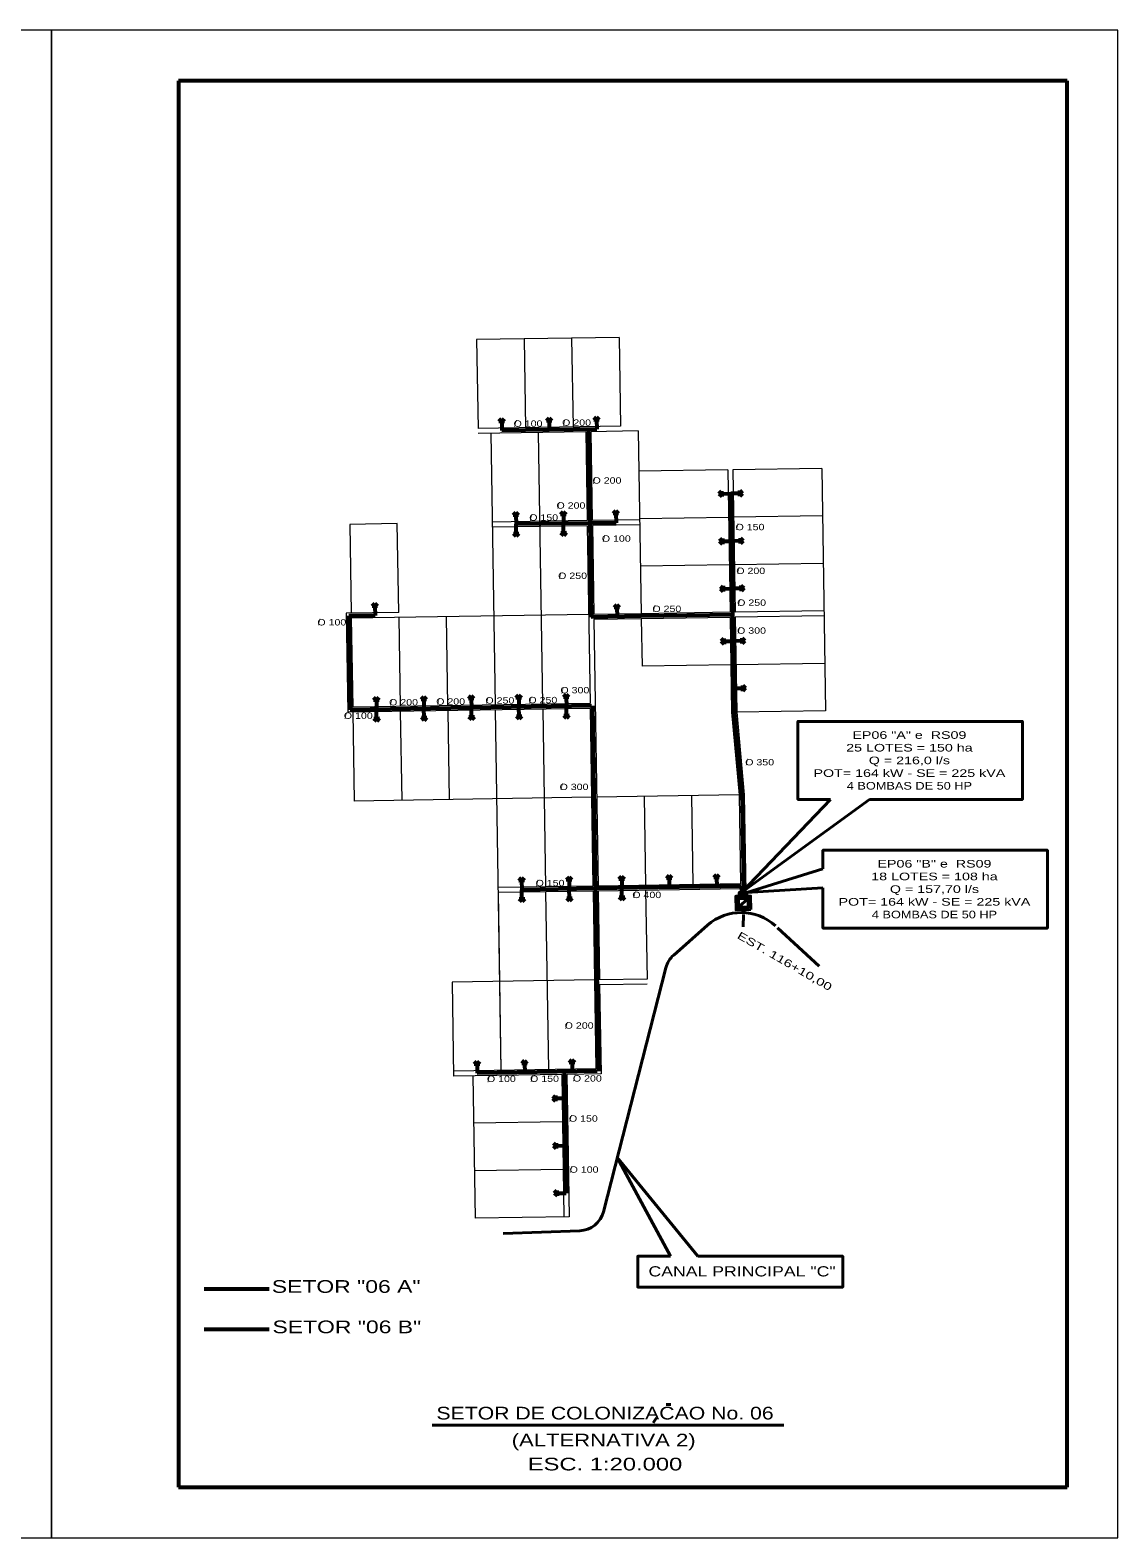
# Model space of a CAD drawing. Extents: x 312964 to 351929, y 9004151 to 9034973.
# Drawn here: x 317080 to 321364, y 9004477 to 9010417 of the extents above; entities that cross this region are included whole.
import ezdxf
from ezdxf.enums import TextEntityAlignment as Align

# ---------------------------------------------------------------- set-up
doc = ezdxf.new("R2010")
doc.units = 0
doc.header["$LTSCALE"] = 10
doc.layers.add('1', color=7, linetype='Continuous', lineweight=13)
doc.layers.add('2', color=7, linetype='Continuous', lineweight=53)

msp = doc.modelspace()

# ---------------------------------------------------------------- linework, layer by layer
at = {"layer": '1', "lineweight": 53}
for p, q in [((317663.57, 9010216.73), (317663.57, 9004676.73)), ((321163.57, 9010216.73), (317663.57, 9010216.73)), ((321163.57, 9004676.73), (321163.57, 9010216.73)), ((319852.53, 9007729.07), (319884.12, 9007376.36)), ((319884.12, 9007376.36), (319889.77, 9007019.76)), ((319880.39, 9007043.79), (319880.77, 9007019.64)), ((317764.64, 9005457.55), (318020.59, 9005457.55)), ((317764.64, 9005298.54), (318020.59, 9005298.54)), ((317663.57, 9004676.73), (321163.57, 9004676.73))]:
    msp.add_line(p, q, dxfattribs=at)
at = {"layer": '1'}
for p, q in [((319399.07, 9009206.44), (318838.14, 9009197.55)), ((319025.12, 9009200.51), (319030.66, 9008850.56)), ((319212.09, 9009203.47), (319217.64, 9008853.52)), ((319399.07, 9009206.44), (319404.62, 9008856.48)), ((318838.14, 9009197.55), (318843.69, 9008847.59)), ((319404.62, 9008856.48), (318843.69, 9008847.59)), ((319267.95, 9008834.31), (318844, 9008827.6)), ((318894, 9008828.39), (318910.94, 9007758.52)), ((319080.97, 9008831.35), (319097.92, 9007761.49)), ((319267.95, 9008834.31), (319273.49, 9008484.36)), ((319474.92, 9008837.59), (319287.95, 9008834.63)), ((319287.95, 9008834.63), (319293.49, 9008484.67)), ((319474.92, 9008837.59), (319486.33, 9008117.68)), ((319827.4, 9008684.16), (319477.44, 9008678.61)), ((320197.35, 9008690.02), (319847.4, 9008684.47)), ((319847.4, 9008684.47), (319856.28, 9008123.54)), ((320197.35, 9008690.02), (320212.48, 9007735.14)), ((319480.47, 9008487.64), (319293.49, 9008484.67)), ((319830.36, 9008497.18), (319480.4, 9008491.64)), ((320200.31, 9008503.04), (319850.36, 9008497.5)), ((318525.59, 9008472.51), (318338.61, 9008469.55)), ((318338.61, 9008469.55), (318344.15, 9008119.59)), ((318531.13, 9008122.55), (318525.59, 9008472.51)), ((319273.49, 9008484.36), (318899.54, 9008478.43)), ((319273.81, 9008464.36), (318899.86, 9008458.44)), ((319273.81, 9008464.36), (319284.9, 9007764.45)), ((319480.78, 9008467.64), (319293.81, 9008464.68)), ((319293.81, 9008464.68), (319299.35, 9008114.72)), ((319833.32, 9008310.2), (319483.37, 9008304.66)), ((320203.28, 9008316.06), (319853.32, 9008310.52)), ((320206.24, 9008129.09), (319856.28, 9008123.54)), ((318531.13, 9008122.55), (318324.16, 9008119.27)), ((318324.16, 9008119.27), (318330.33, 9007729.32)), ((319279.35, 9008114.4), (318344.47, 9008099.59)), ((318344.47, 9008099.59), (318350.02, 9007749.64)), ((318531.45, 9008102.56), (318536.99, 9007752.6)), ((318718.42, 9008105.52), (318723.97, 9007755.56)), ((319486.33, 9008117.68), (319299.35, 9008114.72)), ((319486.64, 9008097.68), (319299.67, 9008094.72)), ((319299.67, 9008094.72), (319316.3, 9007044.85)), ((319836.6, 9008103.23), (319486.64, 9008097.68)), ((319486.64, 9008097.68), (319489.61, 9007910.71)), ((319836.6, 9008103.23), (319842.53, 9007729.28)), ((320206.55, 9008109.09), (319856.6, 9008103.55)), ((319856.6, 9008103.55), (319862.52, 9007729.59)), ((319839.56, 9007916.25), (319489.61, 9007910.71)), ((320209.52, 9007922.11), (319859.56, 9007916.57)), ((319285.21, 9007744.45), (318330.33, 9007729.32)), ((319284.9, 9007764.45), (318350.02, 9007749.64)), ((318350.33, 9007729.64), (318355.88, 9007379.68)), ((318537.31, 9007732.6), (318542.85, 9007382.65)), ((318724.28, 9007735.56), (318729.83, 9007385.61)), ((318911.26, 9007738.53), (318933.75, 9006318.7)), ((319098.24, 9007741.49), (319109.33, 9007041.58)), ((319285.21, 9007744.45), (319296.3, 9007044.54)), ((319842.53, 9007729.28), (319871.69, 9007403.7)), ((320212.48, 9007735.14), (319862.52, 9007729.59)), ((319862.52, 9007729.59), (319891.68, 9007404.01)), ((319290.76, 9007394.49), (318355.88, 9007379.68)), ((319871.69, 9007403.7), (319310.76, 9007394.81)), ((319497.73, 9007397.77), (319503.28, 9007047.82)), ((319684.71, 9007400.73), (319690.25, 9007050.78)), ((319871.69, 9007403.7), (319877.23, 9007053.74)), ((319891.68, 9007404.01), (319897.77, 9007019.78)), ((319296.3, 9007044.54), (318922.35, 9007038.61)), ((319296.62, 9007024.54), (318922.67, 9007018.62)), ((318922.67, 9007018.62), (318933.75, 9006318.7)), ((319109.64, 9007021.58), (319120.73, 9006321.67)), ((319296.62, 9007024.54), (319307.71, 9006324.63)), ((319877.23, 9007053.74), (319316.3, 9007044.85)), ((319877.55, 9007033.74), (319316.62, 9007024.86)), ((319316.62, 9007024.86), (319322.16, 9006674.9)), ((319503.59, 9007027.82), (319509.14, 9006677.86)), ((319877.55, 9007033.74), (319877.77, 9007019.5)), ((319302.16, 9006674.58), (318741.23, 9006665.7)), ((318741.23, 9006665.7), (318747.09, 9006295.74)), ((319509.14, 9006677.86), (319322.16, 9006674.9)), ((319509.45, 9006657.87), (319322.48, 9006654.9)), ((319322.48, 9006654.9), (319328.02, 9006304.95)), ((319307.71, 9006324.63), (318746.78, 9006315.74)), ((319173.04, 9006302.49), (318747.09, 9006295.74)), ((318823.08, 9006296.95), (318831.97, 9005736.02)), ((319173.04, 9006302.49), (319181.93, 9005741.56)), ((319328.02, 9006304.95), (319193.04, 9006302.81)), ((319193.04, 9006302.81), (319201.92, 9005741.88)), ((319176, 9006115.52), (318826.05, 9006109.97)), ((319178.96, 9005928.54), (318829.01, 9005923)), ((319178.96, 9005928.54), (318829.01, 9005923)), ((319201.92, 9005741.88), (318831.97, 9005736.02))]:
    msp.add_line(p, q, dxfattribs=at)
at = {"layer": '1', "lineweight": 40}
for p, q in [((319887.61, 9007004.64), (319872.4, 9007019.42)), ((319872.61, 9007004.42), (319887.4, 9007019.63)), ((319902.61, 9007004.85), (319887.4, 9007019.63)), ((319887.61, 9007004.64), (319902.4, 9007019.85)), ((319907.4, 9006995.02), (319869.56, 9006961.09)), ((319614.3, 9006772.99), (319747.49, 9006890.41)), ((320187.35, 9006728.93), (320023.1, 9006880.27)), ((319337.26, 9005761.56), (319583.56, 9006722.8)), ((318943.23, 9005675.63), (319243.99, 9005686.44)), ((319584.39, 9005001.87), (319602.68, 9005001.87)), ((319546.4, 9004949.78), (319533.74, 9004930.07)), ((318663.13, 9004920.21), (320047.47, 9004920.21))]:
    msp.add_line(p, q, dxfattribs=at)
at = {"layer": '1'}
for points in [[(312963.57, 9010416.73), (312963.57, 9004476.73), (317163.57, 9004476.73), (317163.57, 9010416.73)], [(317163.57, 9010416.73), (317163.57, 9004476.73), (321363.57, 9004476.73), (321363.57, 9010416.73)]]:
    msp.add_lwpolyline(points, close=True, dxfattribs=at)
msp.add_lwpolyline([(319827.4, 9008684.16), (319836.28, 9008123.23), (319486.33, 9008117.68)], dxfattribs=at)
at = {"layer": '1', "lineweight": 40}
for points in [[(319918.02, 9006951.78), (319859.7, 9006950.94), (319858.94, 9007004.33), (319917.26, 9007005.16)], [(319887.4, 9007019.63), (319872.4, 9007019.42), (319872.61, 9007004.42), (319887.61, 9007004.64)], [(319902.4, 9007019.85), (319887.4, 9007019.63), (319887.61, 9007004.64), (319902.61, 9007004.85)], [(319907.88, 9006961.63), (319869.56, 9006961.09), (319869.08, 9006994.47), (319907.4, 9006995.02)], [(319907.4, 9006995.02), (319907.88, 9006961.63), (319869.56, 9006961.09)]]:
    msp.add_lwpolyline(points, close=True, dxfattribs=at)
for points in [[(319602.16, 9005585.86), (319392.1, 9005975.58), (319709.08, 9005585.86)], [(319709.08, 9005585.86), (320280.26, 9005585.86), (320280.26, 9005464.79), (319472.73, 9005464.79), (319472.73, 9005585.86), (319602.16, 9005585.86)]]:
    msp.add_lwpolyline(points, dxfattribs=at)
for centre, radius, start, end in [((319879.75, 9006740.39), 200, 47.34258, 131.40088), ((319680.43, 9006697.98), 100, 131.40087, 165.62837), ((319240.39, 9005786.38), 100, 272.05855, 345.62833)]:
    msp.add_arc(centre, radius, start, end, dxfattribs=at)
at = {"layer": '2'}
for p, q in [((318936.34, 9008885.69), (318925.73, 9008874.75)), ((318947.28, 9008875.09), (318925.73, 9008874.75)), ((318936.34, 9008885.69), (318947.28, 9008875.09)), ((318936.76, 9008874.92), (318937.33, 9008839.08)), ((319311.29, 9008845), (318937.33, 9008839.08)), ((319123.31, 9008888.66), (319112.7, 9008877.71)), ((319134.26, 9008878.05), (319112.7, 9008877.71)), ((319123.31, 9008888.66), (319134.26, 9008878.05)), ((319123.74, 9008877.88), (319124.31, 9008842.04)), ((319277.79, 9008844.47), (319283.49, 9008484.52)), ((319310.29, 9008891.62), (319299.68, 9008880.67)), ((319321.24, 9008881.01), (319299.68, 9008880.67)), ((319310.29, 9008891.62), (319321.24, 9008881.01)), ((319310.72, 9008880.84), (319311.29, 9008845)), ((319792.26, 9008589.83), (319802.87, 9008600.78)), ((319792.26, 9008589.83), (319803.21, 9008579.22)), ((319802.87, 9008600.78), (319803.21, 9008579.22)), ((319803.03, 9008590.26), (319838.88, 9008590.83)), ((319874.72, 9008591.39), (319838.88, 9008590.83)), ((319838.88, 9008590.83), (319846.44, 9008113.39)), ((319874.89, 9008580.87), (319874.55, 9008602.43)), ((319885.5, 9008591.82), (319874.55, 9008602.43)), ((319885.5, 9008591.82), (319874.89, 9008580.87)), ((318992.19, 9008516.53), (318981.58, 9008505.58)), ((319003.14, 9008505.93), (318981.58, 9008505.58)), ((318992.19, 9008516.53), (319003.14, 9008505.93)), ((318992.62, 9008505.76), (318993.19, 9008469.92)), ((319179.17, 9008519.49), (319168.56, 9008508.55)), ((319190.11, 9008508.89), (319168.56, 9008508.55)), ((319179.17, 9008519.49), (319190.11, 9008508.89)), ((319179.6, 9008508.72), (319180.16, 9008472.88)), ((319386.14, 9008522.77), (319375.53, 9008511.82)), ((319397.09, 9008512.17), (319375.53, 9008511.82)), ((319386.14, 9008522.77), (319397.09, 9008512.17)), ((319386.57, 9008512), (319387.14, 9008476.16)), ((318983.23, 9008433.9), (319004.79, 9008434.25)), ((318994.18, 9008423.3), (318983.23, 9008433.9)), ((318993.75, 9008434.07), (318993.19, 9008469.92)), ((318994.18, 9008423.3), (319004.79, 9008434.25)), ((319170.21, 9008436.87), (319191.77, 9008437.21)), ((319181.16, 9008426.26), (319170.21, 9008436.87)), ((319180.73, 9008437.03), (319180.16, 9008472.88)), ((319181.16, 9008426.26), (319191.77, 9008437.21)), ((319283.49, 9008484.52), (319289.51, 9008104.56)), ((319795.22, 9008402.85), (319805.83, 9008413.8)), ((319795.22, 9008402.85), (319806.17, 9008392.24)), ((319805.83, 9008413.8), (319806.17, 9008392.24)), ((319806, 9008403.28), (319841.84, 9008403.85)), ((319877.68, 9008404.42), (319841.84, 9008403.85)), ((319877.85, 9008393.9), (319877.51, 9008415.45)), ((319888.46, 9008404.85), (319877.51, 9008415.45)), ((319888.46, 9008404.85), (319877.85, 9008393.9)), ((319798.18, 9008215.88), (319808.79, 9008226.82)), ((319798.18, 9008215.88), (319809.13, 9008205.27)), ((319808.79, 9008226.82), (319809.13, 9008205.27)), ((319808.96, 9008216.3), (319844.8, 9008216.87)), ((319880.65, 9008217.44), (319844.8, 9008216.87)), ((319880.81, 9008206.92), (319880.47, 9008228.48)), ((319891.42, 9008217.87), (319880.47, 9008228.48)), ((319891.42, 9008217.87), (319880.81, 9008206.92)), ((318436.8, 9008157.69), (318426.2, 9008146.74)), ((318447.75, 9008147.08), (318426.2, 9008146.74)), ((318436.8, 9008157.69), (318447.75, 9008147.08)), ((318437.23, 9008146.92), (318437.8, 9008111.07)), ((319390.14, 9008152.79), (319379.53, 9008141.84)), ((319401.09, 9008142.18), (319379.53, 9008141.84)), ((319390.14, 9008152.79), (319401.09, 9008142.18)), ((319390.57, 9008142.02), (319391.13, 9008106.17)), ((318437.8, 9008111.07), (318334.31, 9008109.43)), ((318334.31, 9008109.43), (318340.17, 9007739.48)), ((319486.49, 9008107.68), (319289.51, 9008104.56)), ((319846.44, 9008113.39), (319486.49, 9008107.68)), ((319846.44, 9008113.39), (319852.53, 9007729.07)), ((319801.46, 9008008.9), (319812.07, 9008019.85)), ((319812.07, 9008019.85), (319812.41, 9007998.29)), ((319883.92, 9008010.47), (319848.08, 9008009.9)), ((319884.09, 9007999.95), (319883.75, 9008021.5)), ((319894.7, 9008010.9), (319883.75, 9008021.5)), ((319894.7, 9008010.9), (319884.09, 9007999.95)), ((319801.46, 9008008.9), (319812.41, 9007998.29)), ((319812.24, 9008009.33), (319848.08, 9008009.9)), ((319887.05, 9007812.97), (319886.71, 9007834.53)), ((319897.66, 9007823.92), (319886.71, 9007834.53)), ((318442.66, 9007787.74), (318432.06, 9007776.79)), ((318453.61, 9007777.13), (318432.06, 9007776.79)), ((318442.66, 9007787.74), (318453.61, 9007777.13)), ((318443.09, 9007776.96), (318443.66, 9007741.12)), ((318629.64, 9007790.7), (318619.03, 9007779.75)), ((318640.59, 9007780.09), (318619.03, 9007779.75)), ((318629.64, 9007790.7), (318640.59, 9007780.09)), ((318630.07, 9007779.93), (318630.64, 9007744.08)), ((318816.62, 9007793.66), (318806.01, 9007782.71)), ((318827.57, 9007783.05), (318806.01, 9007782.71)), ((318816.62, 9007793.66), (318827.57, 9007783.05)), ((318817.05, 9007782.89), (318817.61, 9007747.04)), ((319003.59, 9007796.62), (318992.99, 9007785.67)), ((319014.54, 9007786.02), (318992.99, 9007785.67)), ((319003.59, 9007796.62), (319014.54, 9007786.02)), ((319004.02, 9007785.85), (319004.59, 9007750.01)), ((319190.57, 9007799.59), (319179.96, 9007788.64)), ((319201.52, 9007788.98), (319179.96, 9007788.64)), ((319190.57, 9007799.59), (319201.52, 9007788.98)), ((319191, 9007788.81), (319191.57, 9007752.97)), ((319886.89, 9007823.49), (319851.04, 9007822.92)), ((319897.66, 9007823.92), (319887.05, 9007812.97)), ((319290.06, 9007754.53), (318340.17, 9007739.48)), ((318444.23, 9007705.28), (318443.66, 9007741.12)), ((318631.21, 9007708.24), (318630.64, 9007744.08)), ((318818.18, 9007711.2), (318817.61, 9007747.04)), ((318994.64, 9007713.99), (319016.2, 9007714.34)), ((319005.59, 9007703.39), (318994.64, 9007713.99)), ((319005.16, 9007714.16), (319004.59, 9007750.01)), ((319005.59, 9007703.39), (319016.2, 9007714.34)), ((319181.62, 9007716.96), (319203.17, 9007717.3)), ((319192.56, 9007706.35), (319181.62, 9007716.96)), ((319192.14, 9007717.12), (319191.57, 9007752.97)), ((319192.56, 9007706.35), (319203.17, 9007717.3)), ((319295.05, 9007754.61), (319306.62, 9007024.7)), ((318433.71, 9007705.11), (318455.27, 9007705.45)), ((318444.66, 9007694.5), (318433.71, 9007705.11)), ((318444.66, 9007694.5), (318455.27, 9007705.45)), ((318620.69, 9007708.07), (318642.24, 9007708.41)), ((318631.64, 9007697.46), (318620.69, 9007708.07)), ((318631.64, 9007697.46), (318642.24, 9007708.41)), ((318807.66, 9007711.03), (318829.22, 9007711.37)), ((318818.61, 9007700.43), (318807.66, 9007711.03)), ((318818.61, 9007700.43), (318829.22, 9007711.37)), ((319015, 9007076.71), (319004.39, 9007065.76)), ((319025.95, 9007066.11), (319004.39, 9007065.76)), ((319015, 9007076.71), (319025.95, 9007066.11)), ((319015.43, 9007065.94), (319016, 9007030.1)), ((319201.98, 9007079.68), (319191.37, 9007068.73)), ((319212.92, 9007069.07), (319191.37, 9007068.73)), ((319201.98, 9007079.68), (319212.92, 9007069.07)), ((319202.4, 9007068.9), (319202.97, 9007033.06)), ((319408.95, 9007082.95), (319398.34, 9007072.01)), ((319419.9, 9007072.35), (319398.34, 9007072.01)), ((319408.95, 9007082.95), (319419.9, 9007072.35)), ((319409.38, 9007072.18), (319409.95, 9007036.34)), ((319595.93, 9007085.92), (319585.32, 9007074.97)), ((319606.87, 9007075.31), (319585.32, 9007074.97)), ((319595.93, 9007085.92), (319606.87, 9007075.31)), ((319596.36, 9007075.14), (319596.92, 9007039.3)), ((319782.9, 9007088.88), (319772.3, 9007077.93)), ((319793.85, 9007078.27), (319772.3, 9007077.93)), ((319782.9, 9007088.88), (319793.85, 9007078.27)), ((319783.33, 9007078.1), (319783.9, 9007042.26)), ((319303.46, 9007034.65), (319016, 9007030.1)), ((319016.56, 9006994.25), (319016, 9007030.1)), ((319203.54, 9006997.21), (319202.97, 9007033.06)), ((319306.62, 9007024.7), (319317.86, 9006314.79)), ((319880.39, 9007043.79), (319309.46, 9007034.74)), ((319399.99, 9007000.33), (319421.55, 9007000.67)), ((319410.94, 9006989.72), (319399.99, 9007000.33)), ((319410.51, 9007000.49), (319409.95, 9007036.34)), ((319410.94, 9006989.72), (319421.55, 9007000.67)), ((319006.04, 9006994.09), (319027.6, 9006994.43)), ((319016.99, 9006983.48), (319006.04, 9006994.09)), ((319016.99, 9006983.48), (319027.6, 9006994.43)), ((319193.02, 9006997.05), (319214.58, 9006997.39)), ((319203.97, 9006986.44), (319193.02, 9006997.05)), ((319203.97, 9006986.44), (319214.58, 9006997.39)), ((319888.86, 9006951.36), (319888.38, 9006940.21)), ((318839.43, 9006353.84), (318828.82, 9006342.89)), ((318839.43, 9006353.84), (318850.38, 9006343.23)), ((319026.4, 9006356.8), (319015.8, 9006345.86)), ((319026.4, 9006356.8), (319037.35, 9006346.2)), ((319213.38, 9006359.77), (319202.77, 9006348.82)), ((319224.33, 9006349.16), (319202.77, 9006348.82)), ((319213.38, 9006359.77), (319224.33, 9006349.16)), ((319213.81, 9006348.99), (319214.38, 9006313.15)), ((318850.38, 9006343.23), (318828.82, 9006342.89)), ((318839.86, 9006343.07), (318840.42, 9006307.22)), ((319312.86, 9006314.71), (318840.42, 9006307.22)), ((319037.35, 9006346.2), (319015.8, 9006345.86)), ((319026.83, 9006346.03), (319027.4, 9006310.19)), ((319182.88, 9006312.65), (319190.44, 9005835.21)), ((319137.9, 9006208.17), (319148.51, 9006219.11)), ((319137.9, 9006208.17), (319148.85, 9006197.56)), ((319148.51, 9006219.11), (319148.85, 9006197.56)), ((319148.68, 9006208.59), (319184.52, 9006209.16)), ((319140.86, 9006021.19), (319151.47, 9006032.14)), ((319140.86, 9006021.19), (319151.81, 9006010.58)), ((319151.47, 9006032.14), (319151.81, 9006010.58)), ((319151.64, 9006021.62), (319187.48, 9006022.19)), ((319143.83, 9005834.21), (319154.43, 9005845.16)), ((319143.83, 9005834.21), (319154.78, 9005823.6)), ((319154.43, 9005845.16), (319154.78, 9005823.6)), ((319154.6, 9005834.64), (319190.44, 9005835.21))]:
    msp.add_line(p, q, dxfattribs=at)
at = {"layer": '2', "lineweight": 40}
for p, q in [((320232.26, 9007386.16), (319880.77, 9007019.64)), ((319880.77, 9007019.64), (320384.87, 9007386.16)), ((319888.65, 9006933.18), (319888.38, 9006883.44))]:
    msp.add_line(p, q, dxfattribs=at)
at = {"layer": '2'}
msp.add_lwpolyline([(319387.14, 9008476.16), (319283.65, 9008474.52), (318993.19, 9008469.92)], dxfattribs=at)
at = {"layer": '2', "lineweight": 40}
for points in [[(320103.46, 9007619.58), (320103.46, 9007692.99), (320280.95, 9007692.99)], [(320280.95, 9007692.99), (320987.68, 9007692.99), (320987.68, 9007386.16), (320384.87, 9007386.16)], [(320232.26, 9007386.16), (320103.46, 9007386.16), (320103.46, 9007619.58)], [(320379.64, 9007185.83), (321086.37, 9007185.83), (321086.37, 9006879.01), (320202.15, 9006879.01), (320202.15, 9007038.3)], [(320202.15, 9007112.42), (320202.15, 9007185.83), (320379.64, 9007185.83)], [(320202.15, 9007038.3), (319902.4, 9007019.85), (320202.15, 9007112.42)]]:
    msp.add_lwpolyline(points, dxfattribs=at)

# ---------------------------------------------------------------- texts
at = {"layer": '1'}
for s, height, width, p in [('CANAL PRINCIPAL "C"', 40, 1.3, (319883.53, 9005506.73)), ('SETOR "06 A"', 50, 1.35, (318324.17, 9005442.04)), ('SETOR "06 B"', 50, 1.35, (318326.85, 9005282.91)), ('SETOR DE COLONIZACAO No. 06', 50, 1.25, (319343.81, 9004943.08)), ('(ALTERNATIVA 2)', 50, 1.3, (319338.38, 9004836.97)), ('ESC. 1:20.000', 50, 1.4, (319343.63, 9004742.33))]:
    msp.add_text(s, height=height, dxfattribs=dict(at, width=width)).set_placement(p, align=Align.CENTER)
at = {"layer": '2'}
for s, height, width, p in [('O 100', 25, 1.25, (319040.54, 9008854.1)), ('O 200', 25, 1.25, (319231.72, 9008858.04)), ('O 200', 25, 1.25, (319351.47, 9008630.18)), ('O 200', 25, 1.25, (319209.5, 9008531.59)), ('O 150', 25, 1.25, (319102.19, 9008484.09)), ('O 100', 25, 1.25, (319388.11, 9008401.14)), ('O 150', 25, 1.25, (319914.78, 9008446.61)), ('O 250', 25, 1.25, (319216.02, 9008254.72)), ('O 200', 25, 1.25, (319917.68, 9008274)), ('O 250', 25, 1.25, (319587.2, 9008124.4)), ('O 250', 25, 1.25, (319921.11, 9008148.72)), ('O 100', 25, 1.25, (318267.73, 9008071.32)), ('O 300', 25, 1.25, (319920.82, 9008038.65)), ('O 200', 25, 1.25, (318550.13, 9007756.14)), ('O 200', 25, 1.25, (318735.68, 9007759.3)), ('O 250', 25, 1.25, (318929.66, 9007763.52)), ('O 250', 25, 1.25, (319098.84, 9007764.96)), ('O 300', 25, 1.25, (319224.99, 9007804)), ('O 100', 25, 1.25, (318371.96, 9007703.39)), ('EP06 "A" e  RS09', 30, 1.4, (320542.63, 9007624.65)), ('25 LOTES = 150 ha', 30, 1.4, (320542.63, 9007574.65)), ('O 350', 25, 1.25, (319952.81, 9007519.99)), ('Q = 216,0 l/s', 30, 1.4, (320542.63, 9007524.65)), ('POT= 164 kW - SE = 225 kVA', 30, 1.4, (320542.63, 9007474.65)), ('O 300', 25, 1.25, (319221.64, 9007422.88)), ('4 BOMBAS DE 50 HP', 30, 1.25, (320542.63, 9007424.65)), ('EP06 "B" e  RS09', 30, 1.4, (320641.32, 9007117.49)), ('O 150', 25, 1.25, (319127.25, 9007044.04)), ('18 LOTES = 108 ha', 30, 1.4, (320641.32, 9007067.49)), ('O 400', 25, 1.25, (319508.19, 9006997.22)), ('Q = 157,70 l/s', 30, 1.4, (320641.32, 9007017.49)), ('POT= 164 kW - SE = 225 kVA', 30, 1.4, (320641.32, 9006967.49)), ('4 BOMBAS DE 50 HP', 30, 1.25, (320641.32, 9006917.49)), ('O 200', 25, 1.25, (319241.81, 9006482.66)), ('O 100', 25, 1.25, (318935.49, 9006272.5)), ('O 150', 25, 1.25, (319105.43, 9006273.19)), ('O 200', 25, 1.25, (319274.14, 9006274.42)), ('O 150', 25, 1.25, (319258.45, 9006116.21)), ('O 100', 25, 1.25, (319261.21, 9005915.12))]:
    msp.add_text(s, height=height, dxfattribs=dict(at, width=width)).set_placement(p, align=Align.CENTER)
for p in [(318990.87, 9008853.91), (319182.71, 9008857.2), (319301.14, 9008629.33), (319160.72, 9008531.26), (319052.38, 9008483.76), (319339.61, 9008400.81), (319864.45, 9008447.46), (319166.91, 9008254.43), (319868.67, 9008275.51), (319537.28, 9008125.62), (319871.83, 9008148.92), (318217.74, 9008071.58), (319870.77, 9008039.21), (318501.46, 9007755.23), (318687.68, 9007759.31), (318880.35, 9007763.53), (319050.12, 9007764.98), (319176.52, 9007803.1), (318322.63, 9007703), (319902.76, 9007520.55), (319173.13, 9007423.05), (319076.68, 9007043.5), (319459.99, 9006998.14), (319192.27, 9006482.26), (318885.52, 9006271.21), (319055.47, 9006272.55), (319222.77, 9006275.43), (319207.88, 9006116.21), (319209.99, 9005915.77)]:
    msp.add_text('/', height=25, dxfattribs=at).set_placement(p, align=Align.CENTER)
at = {"layer": '2', "width": 1.45}
msp.add_text('EST. 116+10,00', height=30, rotation=330, dxfattribs=at).set_placement((320044, 9006735.52), align=Align.CENTER)

doc.saveas('drawing.dxf')
